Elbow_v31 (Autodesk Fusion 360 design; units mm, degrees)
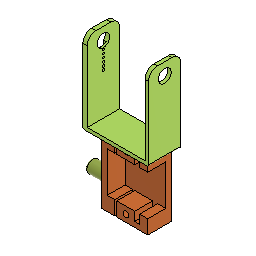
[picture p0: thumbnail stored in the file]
sketch "Sketch1" plane through (0, 0, 0) normal (0, 0, 1) x axis (1, 0, 0)
  line L1 (-18.6, -9.15) -> (18.6, -9.15)
  line L2 (-18.6, 9.15) -> (-18.6, -9.15)
  line L3 (18.6, 9.15) -> (-18.6, 9.15)
  line L4 (18.6, -9.15) -> (18.6, 9.15)
  line L5 (-18.6, 9.15) -> (18.6, -9.15)
  line L6 (18.6, 9.15) -> (-18.6, -9.15)
  line L7 (16.6, 9.15) -> (18.6, 9.15)
  line L8 (16.6, -9.15) -> (16.6, 9.15)
  line L9 (18.6, -9.15) -> (16.6, -9.15)
  line L10 (18.6, 9.15) -> (18.6, -9.15)
  line L11 (-16.1, 9.15) -> (-18.6, 9.15)
  line L12 (-16.1, -9.15) -> (-16.1, 9.15)
  line L13 (-18.6, -9.15) -> (-16.1, -9.15)
  line L14 (-18.6, 9.15) -> (-18.6, -9.15)
  point P6 (0, 0)
  point P1 (0, 0)
  point P4 (-18.6, 9.15)
  point P5 (18.6, 9.15)
  point P3 (-18.6, -9.15)
  point P7 (16.6, 9.15)
  point P10 (-16.1, 9.15)
  point P8 (16.6, -9.15)
  point P11 (-16.1, -9.15)
  horizontal L1
  perpendicular L1 L2
  parallel L1 L3
  parallel L2 L4
  coincident L5 P6
  coincident L6 P6
  coincident P1 P6
  horizontal L7
  vertical L8
  horizontal L9
  vertical L10
  horizontal L11
  vertical L12
  horizontal L13
  vertical L14
  dimension "d1" distance P4 P5 = 37.2 (= "35.5 mm + 2 mm - 0.3 mm")
  dimension "d2" distance P3 P4 = 18.3
  dimension "d3" distance P5 P7 = 2
  dimension "d4" distance P4 P10 = 2.5
  dimension "d52" distance P7 P8 = 18.3 (= "d2")
  dimension "d53" distance P10 P11 = 18.3 (= "d2")
extrude "Extrude1" new body sketch "Sketch1" profile of L1 L3 L8 L12 along normal blind 2
extrude "Extrude4" add sketch "Sketch1" profile of L1 L2 L3 L4 L7 L8 L9 L10 L11 L12 L13 L14 along normal blind 47 (= "2 mm + 25 mm + 20 mm")
sketch "Sketch3" plane through (-18.6, 0, 0) normal (-1, 0, 0) x axis (0, -1, 0)
  line L1 (9.15, 0) -> (-9.15, 0)
  line L2 (9.15, 47) -> (9.15, 0)
  line L3 (-9.15, 47) -> (9.15, 47)
  line L4 (-9.15, 0) -> (-9.15, 47)
  line L5 (-1.997, 25.9409) -> (-2.6411, 37.7278)
  line L6 (2.6411, 37.7278) -> (1.997, 25.9409)
  line L7 (0, 47) -> (0, 0)
  line L8 (-9.15, 40.1) -> (9.15, 40.1)
  circle C1 centre (0, 31.65) radius 0.65
  circle C2 centre (0, 40.1) radius 2.3
  circle C3 centre (0, 27.65) radius 0.65
  arc A1 centre (0, 26.05) radius 2 clockwise from (1.997, 25.9409) to (-1.997, 25.9409)
  circle C4 centre (0, 25.65) radius 0.65
  circle C5 centre (0, 29.65) radius 0.65
  circle C6 centre (0, 35.65) radius 0.65
  circle C7 centre (0, 33.65) radius 0.65
  circle C8 centre (0, 40.1) radius 3.55
  point P1 (0, 0)
  point P17 (0, 0)
  point P18 (0, 47)
  point P19 (9.15, 40.1)
  point P20 (-9.15, 40.1)
  point P23 (2.6411, 37.7278)
  point P24 (-2.6411, 37.7278)
  coincident P1 P17
  midpoint L3 P18
  coincident L2 P19
  coincident L4 P20
  perpendicular L4 L8
  concentric C2 C8
  coincident C8 P23
  coincident C8 P24
  dimension "d19" distance L3 L8 = 6.9 (= "1.45 mm + ( 6.9 / 2 ) * 1 mm + 2 mm")
  dimension "d26" diameter C8 = 7.1
  dimension "d65" diameter C6 = 1.3
  dimension "d66" diameter C7 = 1.3 (= "d65")
  dimension "d67" diameter C1 = 1.3 (= "d65")
  dimension "d68" diameter C5 = 1.3 (= "d65")
  dimension "d69" diameter C3 = 1.3 (= "d65")
  dimension "d70" diameter C4 = 1.3 (= "d65")
extrude "Extrude5" cut sketch "Sketch3" profile of L5 C1 L6 C3 A1 C4 C5 C6 C7 C8 against normal blind 1.4
extrude "Extrude8" cut sketch "Sketch3" profile of C1 C2 C3 C4 C5 C6 C7 C8 against normal blind 2.5
sketch "Sketch7" plane through (18.6, 0, 0) normal (1, 0, 0) x axis (0, 1, 0)
  line L1 (9.15, 0) -> (-9.15, 0)
  line L2 (9.15, 47) -> (9.15, 0)
  line L3 (-9.15, 47) -> (9.15, 47)
  line L4 (-9.15, 0) -> (-9.15, 47)
  circle C1 centre (0, 40.1) radius 3.65
  point P6 (0, 40.1)
  dimension "d44" diameter C1 = 7.3
  dimension "d45" distance L3 P6 = 6.9 (= "4.9 mm + 2 mm")
extrude "Extrude11" cut sketch "Sketch7" profile of C1 against normal blind 3
fillet "Fillet6" radius 5
fillet "Fillet7" radius 5
component_insert "Component Insert4"
joint "Assemble" alignAngle 180 alignOffsetX 0 alignOffsetY 0 alignOffsetZ 0
component_insert "Component Insert6"
joint "Assemble" alignAngle -90 alignOffsetX 24.55 (= "( 20.9 mm + ( 7.3 / 2 ) * 1 mm )") alignOffsetY -9.15 (= "-( ( 18.3 / 2 ) * 1 mm )") alignOffsetZ 0
fillet "Fillet9" radius 1
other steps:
joint_origin "JointOrigin5"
